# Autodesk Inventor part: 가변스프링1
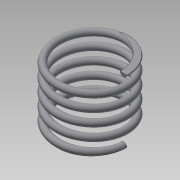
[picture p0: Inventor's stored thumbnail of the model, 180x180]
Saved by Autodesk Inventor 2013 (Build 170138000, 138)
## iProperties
Created: 2019-01
Part Number: 가변스프링1
Material: 일반
Document SubType Name: Modeling
Designer: Administrator
Density: 1 g/cm^3
Mass: 0.9642 g
Surface Area: 19.6313 cm^2
Volume: 0.9642 cm^3
Author: Administrator
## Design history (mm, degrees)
sketch "스케치1"
  geometry: L1 (0, 0)-(10, 0); L2 (10, 0)-(10, 18.7); L3 (10, 18.7)-(0, 18.7); L4 (0, 18.7)-(0, 0); C1 r 1 at (10, 0)
  constraints: 8 end point, 2 parallel, 1 centre point, 1 coincident, 1 horizontal, 1 perpendicular
  dimensions: "d0" = 2 diameter of C1; "d2" = 20 diameter of L2 L4; "d3" = 18.7 distance between parallel lines of L1 L3 (derived)
feature "코일1" sketch "스케치1" pitch "d4" = 10; turns "d6" = 5; dims "d5" = 18.7 (= d3), "d7" = 0, angle "d8" = 90 deg, angle "d9" = 90 deg, "d10" = 0, "d11" = 0
sketch "스케치2"
  geometry: L1 (18.7, 12.5)-(0, 12.5); L2 (0, 12.5)-(0, -12.5); L3 (0, -12.5)-(18.7, -12.5); L4 (18.7, -12.5)-(18.7, 12.5); 2 further points
  constraints: 8 end point, 2 parallel, 1 coincident, 1 horizontal, 1 midpoint, 1 perpendicular
  dimensions: "d12" = 25 distance between parallel lines of L3 L1; "d14" = 18.7 distance between parallel lines of L2 L4 (derived)
extrude "돌출1" sketch "스케치2" stored distance "d15" = 25; taper "d16" = 0 deg
node "솔리드1"
